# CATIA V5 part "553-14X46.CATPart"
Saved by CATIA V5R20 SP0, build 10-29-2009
Part number: 553-14x46
Definition: NONE
Nomenclature: 553-14x46
Source: Unknown
Description: 553-14x46
Bounding box of the stored display mesh (mm): x 0 to 46, y -12.5 to 12.5, z -12.5 to 12.5
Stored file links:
  C:\Users\Utente\Desktop\IO LAVORO\3D X SITO CF\X SITO\PLASTICA\553\553-14X46.CATPart
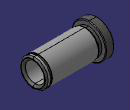
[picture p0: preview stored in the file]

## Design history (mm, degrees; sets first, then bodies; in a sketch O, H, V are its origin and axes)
Body1 "553-14x46" (main body)
  Solid1: solid without history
